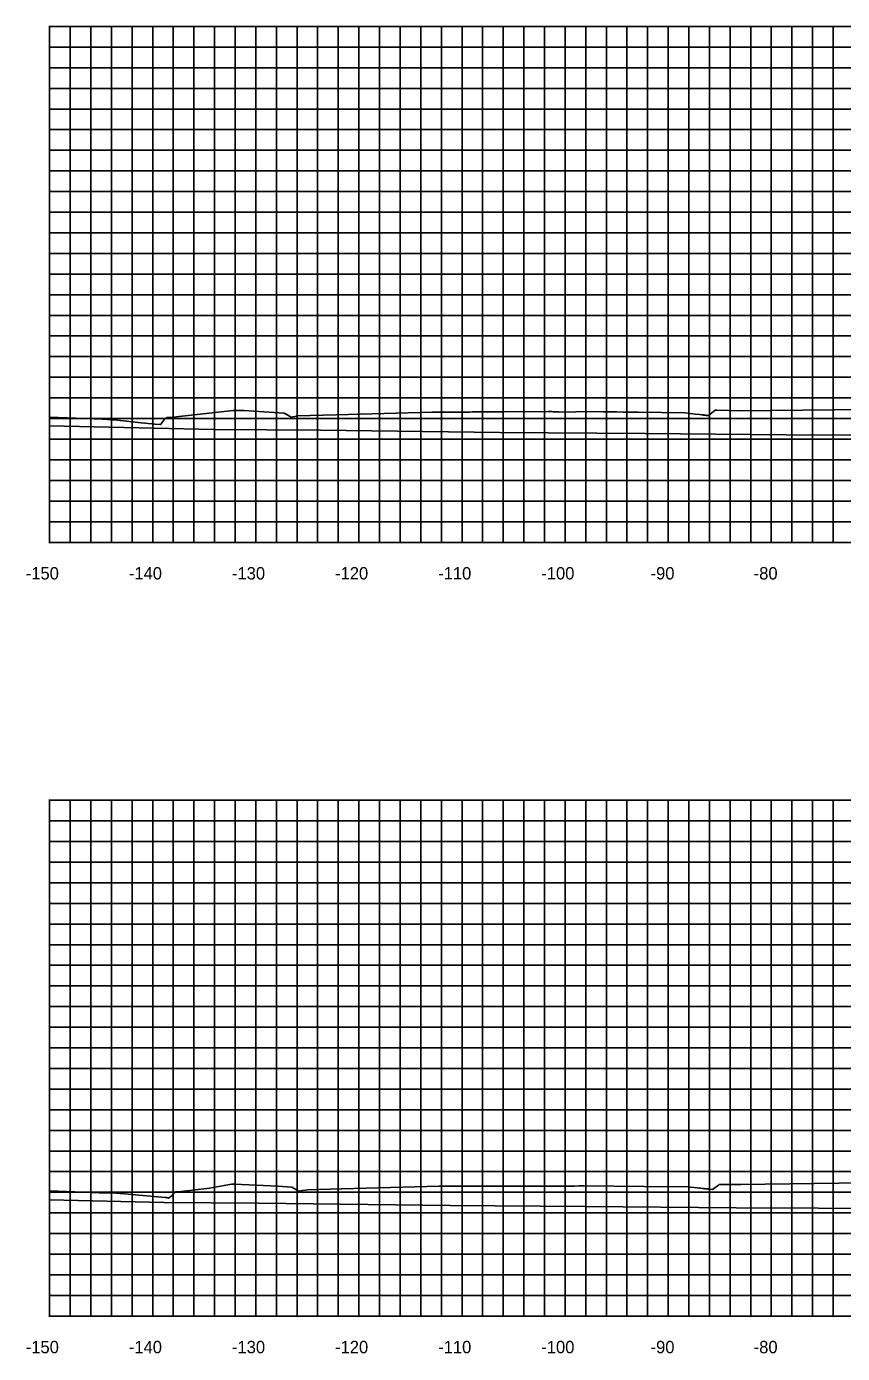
# Model space of a CAD drawing. Extents: x 1800880 to 1818864, y 245271 to 250560.
# Drawn here: x 1808576.2 to 1808655.4, y 249645.6 to 249774.2 of the extents above; entities that cross this region are included whole.
import ezdxf

# ---------------------------------------------------------------- set-up
doc = ezdxf.new("R2010")
doc.units = 0
for name, color, linetype in [('CL-CNST', 7, 'Continuous'), ('DESIGN - DRAINAGE - Bridges', 7, 'Continuous'), ('Level 46', 7, 'Continuous'), ('Level 62', 7, 'Continuous')]:
    doc.layers.add(name, color=color, linetype=linetype)

msp = doc.modelspace()

# ---------------------------------------------------------------- linework, layer by layer
at = {"layer": 'CL-CNST'}
for points in [[(1808578.46, 249736.36), (1808583.6, 249736.16), (1808585.05, 249736.06), (1808587.35, 249735.79), (1808588.38, 249735.7), (1808588.67, 249735.67), (1808589.18, 249735.63), (1808589.21, 249735.62), (1808589.25, 249735.67), (1808589.63, 249736.18), (1808589.85, 249736.32), (1808590.16, 249736.32), (1808595.69, 249736.94), (1808596.27, 249737.01), (1808596.31, 249737.01), (1808596.78, 249737.01), (1808597.32, 249736.99), (1808597.79, 249736.96), (1808601.2, 249736.75), (1808601.41, 249736.63), (1808601.88, 249736.35), (1808602.4, 249736.45), (1808602.46, 249736.47), (1808606.24, 249736.58), (1808615.57, 249736.84), (1808617.96, 249736.85), (1808618.64, 249736.85), (1808619.1, 249736.85), (1808619.19, 249736.85), (1808619.46, 249736.86), (1808620.74, 249736.86), (1808621.08, 249736.87), (1808621.77, 249736.87), (1808622.54, 249736.88), (1808626.83, 249736.91), (1808627.02, 249736.9), (1808627.17, 249736.89), (1808627.3, 249736.88), (1808627.4, 249736.88), (1808627.49, 249736.87), (1808627.56, 249736.87), (1808627.63, 249736.87), (1808627.68, 249736.86), (1808627.73, 249736.86), (1808627.78, 249736.86), (1808627.82, 249736.86), (1808627.85, 249736.85), (1808627.88, 249736.85), (1808631.12, 249736.89), (1808632.15, 249736.88), (1808632.28, 249736.87), (1808632.46, 249736.87), (1808632.71, 249736.87), (1808633.07, 249736.87), (1808633.43, 249736.86), (1808634.08, 249736.85), (1808635.58, 249736.83), (1808640.09, 249736.76), (1808641.06, 249736.65), (1808641.5, 249736.6), (1808641.72, 249736.58), (1808641.85, 249736.57), (1808641.93, 249736.56), (1808641.99, 249736.55), (1808642.04, 249736.55), (1808642.07, 249736.54), (1808642.1, 249736.54), (1808642.13, 249736.54), (1808642.15, 249736.53), (1808642.16, 249736.53), (1808642.18, 249736.53), (1808642.19, 249736.53), (1808642.2, 249736.53), (1808642.21, 249736.53), (1808642.22, 249736.53), (1808642.22, 249736.52), (1808642.23, 249736.52), (1808642.24, 249736.52), (1808642.24, 249736.52), (1808642.25, 249736.52), (1808642.35, 249736.51), (1808642.37, 249736.52), (1808642.99, 249736.99), (1808643.06, 249737.04), (1808643.07, 249737.04), (1808643.17, 249737.04), (1808645.47, 249736.98), (1808657.62, 249737.08)], [(1808578.46, 249661.36), (1808581.73, 249661.24), (1808583.28, 249661.18), (1808584.88, 249661.12), (1808585.74, 249661.06), (1808589.68, 249660.7), (1808589.83, 249660.7), (1808590, 249660.65), (1808590.35, 249660.91), (1808590.52, 249661.15), (1808590.7, 249661.26), (1808590.72, 249661.27), (1808590.97, 249661.26), (1808593.97, 249661.63), (1808596.12, 249662), (1808596.35, 249662), (1808600.59, 249661.8), (1808601.95, 249661.73), (1808602.11, 249661.63), (1808602.64, 249661.32), (1808602.98, 249661.39), (1808603.31, 249661.44), (1808603.48, 249661.46), (1808606.82, 249661.55), (1808616.23, 249661.8), (1808619.33, 249661.8), (1808626, 249661.8), (1808628.02, 249661.81), (1808628.07, 249661.81), (1808628.11, 249661.81), (1808628.14, 249661.81), (1808628.17, 249661.8), (1808628.19, 249661.8), (1808628.21, 249661.8), (1808628.23, 249661.8), (1808628.24, 249661.8), (1808628.26, 249661.8), (1808628.27, 249661.8), (1808628.28, 249661.8), (1808628.29, 249661.8), (1808628.3, 249661.8), (1808629.32, 249661.81), (1808629.38, 249661.81), (1808629.8, 249661.86), (1808630.17, 249661.86), (1808630.28, 249661.86), (1808636.12, 249661.79), (1808640.47, 249661.74), (1808640.56, 249661.73), (1808640.99, 249661.68), (1808641.28, 249661.65), (1808641.49, 249661.63), (1808641.64, 249661.61), (1808641.76, 249661.6), (1808641.86, 249661.58), (1808641.94, 249661.58), (1808642.01, 249661.57), (1808642.06, 249661.56), (1808642.11, 249661.56), (1808642.15, 249661.55), (1808642.19, 249661.55), (1808642.22, 249661.55), (1808642.25, 249661.54), (1808642.33, 249661.54), (1808642.35, 249661.53), (1808642.37, 249661.53), (1808642.4, 249661.53), (1808642.42, 249661.53), (1808642.43, 249661.53), (1808642.76, 249661.48), (1808643.34, 249661.92), (1808643.39, 249661.96), (1808643.39, 249661.96), (1808644.53, 249661.96), (1808645.5, 249661.99), (1808662.11, 249662.21)]]:
    msp.add_lwpolyline(points, dxfattribs=at)
at = {"layer": 'DESIGN - DRAINAGE - Bridges'}
for p, q in [((1808578.4, 249774.22), (1808578.46, 249774.22)), ((1808578.46, 249724.22), (1808578.46, 249774.22)), ((1808578.4, 249764.22), (1808578.46, 249764.22)), ((1808578.4, 249754.22), (1808578.46, 249754.22)), ((1808578.4, 249744.22), (1808578.46, 249744.22)), ((1808578.4, 249734.22), (1808578.46, 249734.22)), ((1808578.4, 249724.22), (1808578.46, 249724.22)), ((1808578.46, 249724.22), (1808878.46, 249724.22)), ((1808578.46, 249724.16), (1808578.46, 249724.22)), ((1808588.46, 249724.16), (1808588.46, 249724.22)), ((1808598.46, 249724.16), (1808598.46, 249724.22)), ((1808608.46, 249724.16), (1808608.46, 249724.22)), ((1808618.46, 249724.16), (1808618.46, 249724.22)), ((1808628.46, 249724.16), (1808628.46, 249724.22)), ((1808638.46, 249724.16), (1808638.46, 249724.22)), ((1808648.46, 249724.16), (1808648.46, 249724.22)), ((1808578.4, 249699.22), (1808578.46, 249699.22)), ((1808578.46, 249649.22), (1808578.46, 249699.22)), ((1808578.4, 249689.22), (1808578.46, 249689.22)), ((1808578.4, 249679.22), (1808578.46, 249679.22)), ((1808578.4, 249669.22), (1808578.46, 249669.22)), ((1808578.4, 249659.22), (1808578.46, 249659.22)), ((1808578.4, 249649.22), (1808578.46, 249649.22)), ((1808578.46, 249649.22), (1808878.46, 249649.22)), ((1808578.46, 249649.16), (1808578.46, 249649.22)), ((1808588.46, 249649.16), (1808588.46, 249649.22)), ((1808598.46, 249649.16), (1808598.46, 249649.22)), ((1808608.46, 249649.16), (1808608.46, 249649.22)), ((1808618.46, 249649.16), (1808618.46, 249649.22)), ((1808628.46, 249649.16), (1808628.46, 249649.22)), ((1808638.46, 249649.16), (1808638.46, 249649.22)), ((1808648.46, 249649.16), (1808648.46, 249649.22))]:
    msp.add_line(p, q, dxfattribs=at)
at = {"layer": 'Level 46'}
for p, q in [((1808578.46, 249774.22), (1808878.46, 249774.22)), ((1808578.46, 249724.22), (1808578.46, 249774.22)), ((1808580.46, 249724.22), (1808580.46, 249774.22)), ((1808582.46, 249724.22), (1808582.46, 249774.22)), ((1808584.46, 249724.22), (1808584.46, 249774.22)), ((1808586.46, 249724.22), (1808586.46, 249774.22)), ((1808588.46, 249724.22), (1808588.46, 249774.22)), ((1808590.46, 249724.22), (1808590.46, 249774.22)), ((1808592.46, 249724.22), (1808592.46, 249774.22)), ((1808594.46, 249724.22), (1808594.46, 249774.22)), ((1808596.46, 249724.22), (1808596.46, 249774.22)), ((1808598.46, 249724.22), (1808598.46, 249774.22)), ((1808600.46, 249724.22), (1808600.46, 249774.22)), ((1808602.46, 249724.22), (1808602.46, 249774.22)), ((1808604.46, 249724.22), (1808604.46, 249774.22)), ((1808606.46, 249724.22), (1808606.46, 249774.22)), ((1808608.46, 249724.22), (1808608.46, 249774.22)), ((1808610.46, 249724.22), (1808610.46, 249774.22)), ((1808612.46, 249724.22), (1808612.46, 249774.22)), ((1808614.46, 249724.22), (1808614.46, 249774.22)), ((1808616.46, 249724.22), (1808616.46, 249774.22)), ((1808618.46, 249724.22), (1808618.46, 249774.22)), ((1808620.46, 249724.22), (1808620.46, 249774.22)), ((1808622.46, 249724.22), (1808622.46, 249774.22)), ((1808624.46, 249724.22), (1808624.46, 249774.22)), ((1808626.46, 249724.22), (1808626.46, 249774.22)), ((1808628.46, 249724.22), (1808628.46, 249774.22)), ((1808630.46, 249724.22), (1808630.46, 249774.22)), ((1808632.46, 249724.22), (1808632.46, 249774.22)), ((1808634.46, 249724.22), (1808634.46, 249774.22)), ((1808636.46, 249724.22), (1808636.46, 249774.22)), ((1808638.46, 249724.22), (1808638.46, 249774.22)), ((1808640.46, 249724.22), (1808640.46, 249774.22)), ((1808642.46, 249724.22), (1808642.46, 249774.22)), ((1808644.46, 249724.22), (1808644.46, 249774.22)), ((1808646.46, 249724.22), (1808646.46, 249774.22)), ((1808648.46, 249724.22), (1808648.46, 249774.22)), ((1808650.46, 249724.22), (1808650.46, 249774.22)), ((1808652.46, 249724.22), (1808652.46, 249774.22)), ((1808654.46, 249724.22), (1808654.46, 249774.22)), ((1808578.46, 249772.22), (1808878.46, 249772.22)), ((1808578.46, 249770.22), (1808878.46, 249770.22)), ((1808578.46, 249768.22), (1808878.46, 249768.22)), ((1808578.46, 249766.22), (1808878.46, 249766.22)), ((1808578.46, 249764.22), (1808878.46, 249764.22)), ((1808578.46, 249762.22), (1808878.46, 249762.22)), ((1808578.46, 249760.22), (1808878.46, 249760.22)), ((1808578.46, 249758.22), (1808878.46, 249758.22)), ((1808578.46, 249756.22), (1808878.46, 249756.22)), ((1808578.46, 249754.22), (1808878.46, 249754.22)), ((1808578.46, 249752.22), (1808878.46, 249752.22)), ((1808578.46, 249750.22), (1808878.46, 249750.22)), ((1808578.46, 249748.22), (1808878.46, 249748.22)), ((1808578.46, 249746.22), (1808878.46, 249746.22)), ((1808578.46, 249744.22), (1808878.46, 249744.22)), ((1808578.46, 249742.22), (1808878.46, 249742.22)), ((1808578.46, 249740.22), (1808878.46, 249740.22)), ((1808578.46, 249738.22), (1808878.46, 249738.22)), ((1808578.46, 249736.22), (1808878.46, 249736.22)), ((1808578.46, 249734.22), (1808878.46, 249734.22)), ((1808578.46, 249732.22), (1808878.46, 249732.22)), ((1808578.46, 249730.22), (1808878.46, 249730.22)), ((1808578.46, 249728.22), (1808878.46, 249728.22)), ((1808578.46, 249726.22), (1808878.46, 249726.22)), ((1808578.46, 249724.22), (1808878.46, 249724.22)), ((1808578.46, 249699.22), (1808878.46, 249699.22)), ((1808578.46, 249649.22), (1808578.46, 249699.22)), ((1808580.46, 249649.22), (1808580.46, 249699.22)), ((1808582.46, 249649.22), (1808582.46, 249699.22)), ((1808584.46, 249649.22), (1808584.46, 249699.22)), ((1808586.46, 249649.22), (1808586.46, 249699.22)), ((1808588.46, 249649.22), (1808588.46, 249699.22)), ((1808590.46, 249649.22), (1808590.46, 249699.22)), ((1808592.46, 249649.22), (1808592.46, 249699.22)), ((1808594.46, 249649.22), (1808594.46, 249699.22)), ((1808596.46, 249649.22), (1808596.46, 249699.22)), ((1808598.46, 249649.22), (1808598.46, 249699.22)), ((1808600.46, 249649.22), (1808600.46, 249699.22)), ((1808602.46, 249649.22), (1808602.46, 249699.22)), ((1808604.46, 249649.22), (1808604.46, 249699.22)), ((1808606.46, 249649.22), (1808606.46, 249699.22)), ((1808608.46, 249649.22), (1808608.46, 249699.22)), ((1808610.46, 249649.22), (1808610.46, 249699.22)), ((1808612.46, 249649.22), (1808612.46, 249699.22)), ((1808614.46, 249649.22), (1808614.46, 249699.22)), ((1808616.46, 249649.22), (1808616.46, 249699.22)), ((1808618.46, 249649.22), (1808618.46, 249699.22)), ((1808620.46, 249649.22), (1808620.46, 249699.22)), ((1808622.46, 249649.22), (1808622.46, 249699.22)), ((1808624.46, 249649.22), (1808624.46, 249699.22)), ((1808626.46, 249649.22), (1808626.46, 249699.22)), ((1808628.46, 249649.22), (1808628.46, 249699.22)), ((1808630.46, 249649.22), (1808630.46, 249699.22)), ((1808632.46, 249649.22), (1808632.46, 249699.22)), ((1808634.46, 249649.22), (1808634.46, 249699.22)), ((1808636.46, 249649.22), (1808636.46, 249699.22)), ((1808638.46, 249649.22), (1808638.46, 249699.22)), ((1808640.46, 249649.22), (1808640.46, 249699.22)), ((1808642.46, 249649.22), (1808642.46, 249699.22)), ((1808644.46, 249649.22), (1808644.46, 249699.22)), ((1808646.46, 249649.22), (1808646.46, 249699.22)), ((1808648.46, 249649.22), (1808648.46, 249699.22)), ((1808650.46, 249649.22), (1808650.46, 249699.22)), ((1808652.46, 249649.22), (1808652.46, 249699.22)), ((1808654.46, 249649.22), (1808654.46, 249699.22)), ((1808578.46, 249697.22), (1808878.46, 249697.22)), ((1808578.46, 249695.22), (1808878.46, 249695.22)), ((1808578.46, 249693.22), (1808878.46, 249693.22)), ((1808578.46, 249691.22), (1808878.46, 249691.22)), ((1808578.46, 249689.22), (1808878.46, 249689.22)), ((1808578.46, 249687.22), (1808878.46, 249687.22)), ((1808578.46, 249685.22), (1808878.46, 249685.22)), ((1808578.46, 249683.22), (1808878.46, 249683.22)), ((1808578.46, 249681.22), (1808878.46, 249681.22)), ((1808578.46, 249679.22), (1808878.46, 249679.22)), ((1808578.46, 249677.22), (1808878.46, 249677.22)), ((1808578.46, 249675.22), (1808878.46, 249675.22)), ((1808578.46, 249673.22), (1808878.46, 249673.22)), ((1808578.46, 249671.22), (1808878.46, 249671.22)), ((1808578.46, 249669.22), (1808878.46, 249669.22)), ((1808578.46, 249667.22), (1808878.46, 249667.22)), ((1808578.46, 249665.22), (1808878.46, 249665.22)), ((1808578.46, 249663.22), (1808878.46, 249663.22)), ((1808578.46, 249661.22), (1808878.46, 249661.22)), ((1808578.46, 249659.22), (1808878.46, 249659.22)), ((1808578.46, 249657.22), (1808878.46, 249657.22)), ((1808578.46, 249655.22), (1808878.46, 249655.22)), ((1808578.46, 249653.22), (1808878.46, 249653.22)), ((1808578.46, 249651.22), (1808878.46, 249651.22)), ((1808578.46, 249649.22), (1808878.46, 249649.22))]:
    msp.add_line(p, q, dxfattribs=at)
at = {"layer": 'Level 62'}
for points in [[(1808578.46, 249735.52), (1808594.38, 249735.17), (1808604.73, 249735.08), (1808622.13, 249734.86), (1808636.22, 249734.77), (1808649.89, 249734.64), (1808666.72, 249734.56), (1808677.64, 249734.48), (1808696.59, 249734.42), (1808705.4, 249734.33), (1808726.02, 249734.3), (1808733.15, 249734.25), (1808755.13, 249734.25), (1808760.91, 249734.21), (1808784, 249734.25), (1808788.66, 249734.21), (1808812.7, 249734.29), (1808816.42, 249734.28), (1808841.26, 249734.4), (1808844.18, 249734.4), (1808869.71, 249734.54), (1808871.93, 249734.5), (1808878.46, 249734.54)], [(1808578.46, 249660.49), (1808589.55, 249660.24), (1808598.72, 249660.17), (1808617.31, 249659.94), (1808630.39, 249659.85), (1808645.06, 249659.71), (1808661.03, 249659.64), (1808672.82, 249659.55), (1808690.99, 249659.49), (1808700.58, 249659.4), (1808720.5, 249659.36), (1808728.33, 249659.31), (1808749.68, 249659.31), (1808756.09, 249659.27), (1808778.61, 249659.3), (1808783.84, 249659.26), (1808807.35, 249659.34), (1808811.6, 249659.33), (1808835.95, 249659.44), (1808839.35, 249659.45), (1808864.44, 249659.58), (1808867.11, 249659.54), (1808878.46, 249659.6)]]:
    msp.add_lwpolyline(points, dxfattribs=at)

# ---------------------------------------------------------------- texts
for s, p in [('-150', (1808576.15, 249720.62)), ('-140', (1808586.15, 249720.62)), ('-130', (1808596.15, 249720.62)), ('-120', (1808606.15, 249720.62)), ('-110', (1808616.15, 249720.62)), ('-100', (1808626.15, 249720.62)), ('-90', (1808636.75, 249720.62)), ('-80', (1808646.75, 249720.62)), ('-150', (1808576.15, 249645.62)), ('-140', (1808586.15, 249645.62)), ('-130', (1808596.15, 249645.62)), ('-120', (1808606.15, 249645.62)), ('-110', (1808616.15, 249645.62)), ('-100', (1808626.15, 249645.62)), ('-90', (1808636.75, 249645.62)), ('-80', (1808646.75, 249645.62))]:
    msp.add_text(s, height=1.2).set_placement(p)
at = {"layer": 'DESIGN - DRAINAGE - Bridges'}
for p in [(1808578.46, 249724.22), (1808578.46, 249649.22)]:
    msp.add_text('-', height=0.0001, dxfattribs=at).set_placement(p)

doc.saveas('drawing.dxf')
